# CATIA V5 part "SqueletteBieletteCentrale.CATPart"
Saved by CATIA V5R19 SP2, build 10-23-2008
Part number: SqueletteBieletteCentrale
Bounding box of the stored display mesh (mm): x 0 to 68, y 0 to 0, z 0 to 0
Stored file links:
  E:\Mes documents\03_Ressources pédagogiques\01_Catia\Buggy Dassault\SchemaCinematiqueFinal\SqueletteBieletteCentrale.CATPart
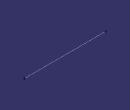
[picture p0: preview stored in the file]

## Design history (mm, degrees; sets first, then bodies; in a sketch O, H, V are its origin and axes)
AxisSystem1: origin (0, 0, 0), X (1, 0, 0), Y (0, 1, 0), Z (0, 0, 1)
Body1 (main body)
  Line1: type PtDir, RefPoint vertex [YZ plane of AxisSystem1 | ZX plane of AxisSystem1 | XY plane of AxisSystem1], Direction edge [XY plane of AxisSystem1 | ZX plane of AxisSystem1], Start 0, End 68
